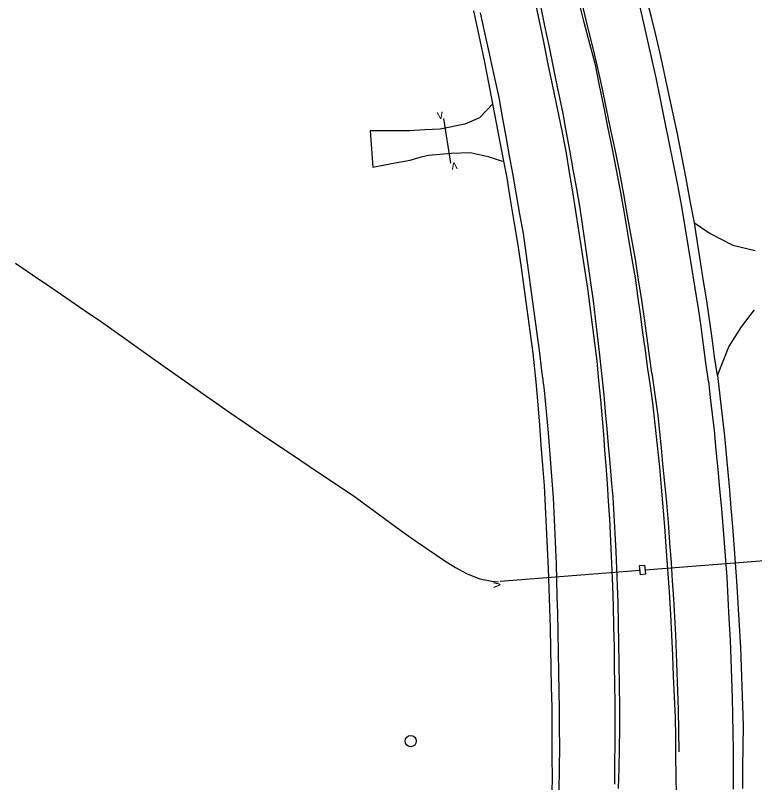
# Model space of a CAD drawing. Extents: x 2262665 to 2270527, y 505476 to 514960.
# Drawn here: x 2266084.7 to 2266408.7, y 512017.6 to 512354 of the extents above; entities that cross this region are included whole.
import ezdxf

# ---------------------------------------------------------------- set-up
doc = ezdxf.new("R2010")
doc.units = 0
for name, color, linetype in [('Exist Hydro Stream or Body of Water', 7, 'Continuous'), ('Exist Roads EOP', 7, 'Continuous'), ('Exist Roads EOT', 7, 'Continuous'), ('Exist Roads Soil', 7, 'Continuous'), ('Exist Structure Minor Culvert Topo', 7, 'Continuous'), ('Exist Structure Minor Culvert Topo Terminator', 7, 'Continuous'), ('Exist Structure Minor Drop Inlet', 7, 'Continuous'), ('Exist Utilities Other Pole CELL', 7, 'Continuous')]:
    doc.layers.add(name, color=color, linetype=linetype)

msp = doc.modelspace()

# ---------------------------------------------------------------- linework, layer by layer
at = {"layer": 'Exist Hydro Stream or Body of Water'}
for points in [[(2266084.69, 512245.42), (2266092.23, 512240.27), (2266099.78, 512235.11), (2266107.32, 512229.96), (2266114.87, 512224.8), (2266122.41, 512219.65), (2266129.51, 512214.59), (2266136.61, 512209.54), (2266143.71, 512204.49), (2266150.81, 512199.44), (2266157.66, 512194.64), (2266164.51, 512189.84), (2266171.37, 512185.04), (2266178.22, 512180.24), (2266185.07, 512175.44), (2266193.19, 512169.99), (2266201.32, 512164.55), (2266209.45, 512159.1), (2266217.57, 512153.65), (2266225.7, 512148.2), (2266233.82, 512142.76), (2266239.9, 512138.29), (2266245.98, 512133.82), (2266252.06, 512129.35), (2266258.14, 512124.88), (2266265.58, 512119.84), (2266273.01, 512114.8), (2266277.62, 512112)], [(2266277.62, 512112), (2266282.72, 512109.15), (2266288.34, 512106.99), (2266293.6, 512105.88), (2266296.52, 512105.6)]]:
    msp.add_lwpolyline(points, dxfattribs=at)
at = {"layer": 'Exist Roads EOP'}
for points in [[(2266392.39, 512196.1), (2266391.22, 512204.29), (2266390.06, 512212.48), (2266388.89, 512220.67), (2266387.72, 512228.86), (2266386.39, 512237.39), (2266385.07, 512245.92), (2266383.74, 512254.45), (2266382.41, 512262.97), (2266380.55, 512272.74), (2266378.69, 512282.5), (2266376.83, 512292.26), (2266374.97, 512302.02), (2266373.04, 512310.83), (2266371.12, 512319.63), (2266369.19, 512328.44), (2266367.26, 512337.25), (2266365.34, 512346.05), (2266363.35, 512353.81), (2266361.37, 512361.56)], [(2266314.72, 512358.85), (2266316.67, 512349.43), (2266318.62, 512340.02), (2266320.57, 512330.6), (2266322.52, 512321.18), (2266324.47, 512311.76), (2266326, 512303.31), (2266327.53, 512294.87), (2266329.06, 512286.42), (2266330.59, 512277.97), (2266332.12, 512269.53), (2266333.29, 512261.38), (2266334.45, 512253.23), (2266335.61, 512245.08), (2266336.78, 512236.93), (2266337.94, 512228.78), (2266338.82, 512221.29), (2266339.7, 512213.81), (2266340.59, 512206.33)], [(2266361.98, 512199.04), (2266360.88, 512207.02), (2266359.78, 512215.01), (2266358.69, 512222.99), (2266357.59, 512230.98), (2266356.49, 512238.96), (2266354.83, 512248.71), (2266353.18, 512258.46), (2266351.52, 512268.21), (2266349.87, 512277.96), (2266348.04, 512287.01), (2266346.22, 512296.06), (2266344.39, 512305.11), (2266342.57, 512314.16), (2266340.74, 512323.21), (2266338.92, 512332.26), (2266336.5, 512341.57), (2266334.08, 512350.88), (2266331.66, 512360.19)], [(2266311.72, 512205.84), (2266310.4, 512215.51), (2266309.09, 512225.19), (2266307.77, 512234.86), (2266306.46, 512244.53), (2266304.9, 512254.09), (2266303.34, 512263.65), (2266301.77, 512273.21), (2266300.21, 512282.77), (2266298.82, 512290.04), (2266297.22, 512298.43), (2266295.62, 512306.82), (2266294.02, 512315.21), (2266292.27, 512324.36), (2266290.52, 512333.51), (2266288.92, 512341.01), (2266287.31, 512348.51), (2266285.7, 512356.01)], [(2266319.96, 512012.92), (2266320.09, 512020.45), (2266320.05, 512028.05), (2266320.01, 512035.64), (2266319.98, 512043.24), (2266319.94, 512050.84), (2266319.75, 512059.47), (2266319.56, 512068.09), (2266319.38, 512076.72), (2266319.19, 512085.35), (2266318.93, 512094.05), (2266318.67, 512102.74), (2266318.41, 512111.44), (2266317.96, 512120.54), (2266317.51, 512129.63), (2266317.06, 512138.73), (2266316.61, 512147.83), (2266315.92, 512156.66), (2266315.23, 512165.5), (2266314.53, 512174.34), (2266313.84, 512183.18), (2266312.95, 512193.31), (2266311.72, 512205.84)], [(2266340.59, 512206.33), (2266341.61, 512196.92), (2266342.63, 512187.52), (2266343.27, 512180.13), (2266343.91, 512172.75), (2266344.55, 512165.37), (2266345.21, 512157.86), (2266345.86, 512150.35), (2266346.52, 512142.84), (2266346.99, 512134.88), (2266347.46, 512126.93), (2266347.93, 512118.98), (2266348.2, 512111.45), (2266348.46, 512103.93), (2266348.73, 512096.41), (2266348.91, 512087.55), (2266349.09, 512078.69), (2266349.27, 512069.82), (2266349.35, 512060.29), (2266349.44, 512050.76), (2266349.53, 512041.22), (2266349.34, 512032.52), (2266349.16, 512023.82), (2266348.98, 512015.12)], [(2266374.54, 512012.11), (2266374.41, 512020.63), (2266374.27, 512029.16), (2266374.14, 512037.68), (2266374, 512046.21), (2266373.61, 512055.24), (2266373.22, 512064.27), (2266372.82, 512073.3), (2266372.43, 512082.33), (2266372.04, 512091.37), (2266371.37, 512101.31), (2266370.69, 512111.25), (2266370.02, 512121.19), (2266369.31, 512129.86), (2266368.6, 512138.53), (2266367.9, 512147.21), (2266367.19, 512155.88), (2266366.16, 512165.3), (2266365.14, 512174.73), (2266364.11, 512184.16), (2266363.05, 512191.6), (2266361.98, 512199.04)], [(2266392.39, 512196.1), (2266393.42, 512187.23), (2266394.45, 512178.35), (2266395.48, 512169.47), (2266396.2, 512161.59), (2266396.93, 512153.71), (2266397.65, 512145.83), (2266398.37, 512137.94), (2266398.99, 512129.97), (2266399.61, 512121.99), (2266400.23, 512114.01), (2266400.85, 512106.04), (2266401.42, 512096.31), (2266401.99, 512086.58), (2266402.56, 512076.84), (2266402.85, 512068.32), (2266403.14, 512059.79), (2266403.43, 512051.27), (2266403.72, 512042.74), (2266403.6, 512033.5), (2266403.48, 512024.25), (2266403.37, 512015.01)]]:
    msp.add_lwpolyline(points, dxfattribs=at)
at = {"layer": 'Exist Roads EOT'}
for points in [[(2266312.14, 512361.88), (2266314.14, 512352.13), (2266316.15, 512342.37), (2266318.15, 512332.62), (2266320.16, 512322.87), (2266322.17, 512313.12), (2266324.17, 512303.37), (2266326.18, 512293.62), (2266327.51, 512285.13), (2266328.84, 512276.64), (2266330.18, 512268.15), (2266331.51, 512259.66), (2266332.84, 512251.17), (2266334.18, 512242.68), (2266335.51, 512234.19), (2266336.52, 512226.24), (2266337.53, 512218.29), (2266338.54, 512210.33), (2266339.56, 512202.38)], [(2266388.5, 512193.67), (2266387.42, 512201.64), (2266386.34, 512209.6), (2266385.26, 512217.56), (2266384.18, 512225.53), (2266382.72, 512234.46), (2266381.27, 512243.38), (2266379.81, 512252.31), (2266378.36, 512261.24), (2266376.9, 512270.17), (2266375.02, 512279.57), (2266373.13, 512288.98), (2266371.25, 512298.39), (2266369.36, 512307.8), (2266367.47, 512317.2), (2266365.59, 512326.61), (2266363.54, 512335.64), (2266361.48, 512344.67), (2266359.43, 512353.7), (2266357.38, 512362.74)], [(2266314.44, 512207.04), (2266313.27, 512215.58), (2266312.1, 512224.13), (2266310.92, 512232.67), (2266309.75, 512241.22), (2266308.58, 512249.76), (2266307.41, 512258.31), (2266305.88, 512266.83), (2266304.36, 512275.35), (2266302.84, 512283.87), (2266301.31, 512292.39), (2266299.79, 512300.91), (2266298.27, 512309.43), (2266296.74, 512317.95), (2266294.71, 512327.23), (2266292.67, 512336.5), (2266290.63, 512345.78), (2266288.59, 512355.05)], [(2266363.74, 512197.07), (2266362.7, 512204.76), (2266361.65, 512212.45), (2266360.6, 512220.14), (2266359.23, 512229.11), (2266357.86, 512238.08), (2266356.49, 512247.04), (2266354.79, 512256.57), (2266353.08, 512266.1), (2266351.37, 512275.63), (2266349.67, 512285.16), (2266347.71, 512294.44), (2266345.75, 512303.73), (2266343.79, 512313.01), (2266341.84, 512322.3), (2266339.88, 512331.58), (2266337.76, 512340.17), (2266335.65, 512348.77), (2266333.53, 512357.36)], [(2266323.01, 512014.05), (2266323.16, 512023.72), (2266323.32, 512033.4), (2266323.23, 512041.54), (2266323.15, 512049.69), (2266323.06, 512057.84), (2266322.97, 512065.98), (2266322.79, 512074.69), (2266322.61, 512083.39), (2266322.43, 512092.09), (2266322.25, 512099.24), (2266322.07, 512106.39), (2266321.89, 512113.54), (2266321.44, 512123.17), (2266320.99, 512132.8), (2266320.54, 512142.43), (2266319.83, 512151.93), (2266319.13, 512161.42), (2266318.42, 512170.91), (2266317.51, 512180.29), (2266316.6, 512189.67), (2266315.52, 512198.35), (2266314.44, 512207.04)], [(2266339.56, 512202.38), (2266340.36, 512193.94), (2266341.17, 512185.5), (2266341.98, 512177.06), (2266342.49, 512170.24), (2266343, 512163.42), (2266343.51, 512156.6), (2266344.04, 512148.8), (2266344.56, 512141.01), (2266345.09, 512133.21), (2266345.53, 512123.45), (2266345.97, 512113.7), (2266346.41, 512103.94), (2266346.66, 512095.01), (2266346.9, 512086.07), (2266347.15, 512077.14), (2266347.24, 512068.92), (2266347.33, 512060.69), (2266347.41, 512052.47), (2266347.5, 512044.25), (2266347.43, 512035.13), (2266347.36, 512026.01), (2266347.29, 512016.89)], [(2266363.74, 512197.07), (2266365.06, 512187.8), (2266366.37, 512178.53), (2266367.04, 512171.48), (2266367.7, 512164.44), (2266368.37, 512157.39), (2266369.23, 512148.93), (2266370.1, 512140.47), (2266370.79, 512131.65), (2266371.49, 512122.83), (2266372.19, 512114.01), (2266372.65, 512106.11), (2266373.11, 512098.21), (2266373.56, 512090.3), (2266374.02, 512082.4), (2266374.34, 512074.19), (2266374.65, 512065.98), (2266374.97, 512057.78), (2266375.28, 512049.57), (2266375.42, 512040.33), (2266375.55, 512031.08)], [(2266388.5, 512193.67), (2266389.32, 512186.45), (2266390.14, 512179.22), (2266390.96, 512171.99), (2266391.76, 512163.43), (2266392.57, 512154.86), (2266393.37, 512146.29), (2266394.18, 512137.72), (2266394.77, 512130.2), (2266395.36, 512122.68), (2266395.95, 512115.16), (2266396.54, 512107.64), (2266397.02, 512098.52), (2266397.5, 512089.39), (2266397.98, 512080.27), (2266398.3, 512071.8), (2266398.62, 512063.32), (2266398.93, 512054.84), (2266399.05, 512047.18), (2266399.17, 512039.52), (2266399.28, 512031.85), (2266399.4, 512024.19), (2266399.29, 512014.72)]]:
    msp.add_lwpolyline(points, dxfattribs=at)
at = {"layer": 'Exist Roads Soil'}
for points in [[(2266294.02, 512315.21), (2266288.14, 512309.01), (2266281.74, 512306.25), (2266270.97, 512304.09), (2266264.2, 512303.74), (2266257.42, 512303.4), (2266248.81, 512303.39), (2266240.19, 512303.38), (2266240.81, 512295.41), (2266241.44, 512287.44), (2266249.57, 512289), (2266257.7, 512290.57), (2266263.14, 512292.08), (2266265.77, 512292.73), (2266275.76, 512293.59), (2266284.11, 512293.91), (2266292, 512292.1), (2266297.59, 512290.24), (2266298.82, 512290.04)], [(2266382.41, 512262.97), (2266389.2, 512258.35), (2266393.84, 512255.99)], [(2266393.84, 512255.99), (2266399.14, 512253.3), (2266408.96, 512250.91)], [(2266392.39, 512196.1), (2266394.95, 512202.4), (2266397.5, 512208.71), (2266402.95, 512217.48), (2266408.75, 512224.83)]]:
    msp.add_lwpolyline(points, dxfattribs=at)
at = {"layer": 'Exist Structure Minor Culvert Topo'}
for p, q in [((2266275.55, 512289.25), (2266272.47, 512308.8)), ((2266434.95, 512116.54), (2266360.72, 512110.74)), ((2266358.5, 512110.57), (2266297.23, 512105.78))]:
    msp.add_line(p, q, dxfattribs=at)
at = {"layer": 'Exist Structure Minor Drop Inlet'}
msp.add_lwpolyline([(2266360.5, 512113.02), (2266360.89, 512108.98), (2266358.68, 512108.77), (2266358.29, 512112.81)], close=True, dxfattribs=at)
at = {"layer": 'Exist Utilities Other Pole CELL'}
msp.add_circle((2266257.99, 512035.82), 2.46, dxfattribs=at)

# ---------------------------------------------------------------- texts
at = {"layer": 'Exist Structure Minor Culvert Topo Terminator'}
for rotation, p in [(8.9483, (2266269.86, 512308.39)), (188.9483, (2266278.17, 512289.67)), (94.4671, (2266297.44, 512103.15))]:
    msp.add_text('v', height=4, rotation=rotation, dxfattribs=at).set_placement(p)

doc.saveas('drawing.dxf')
